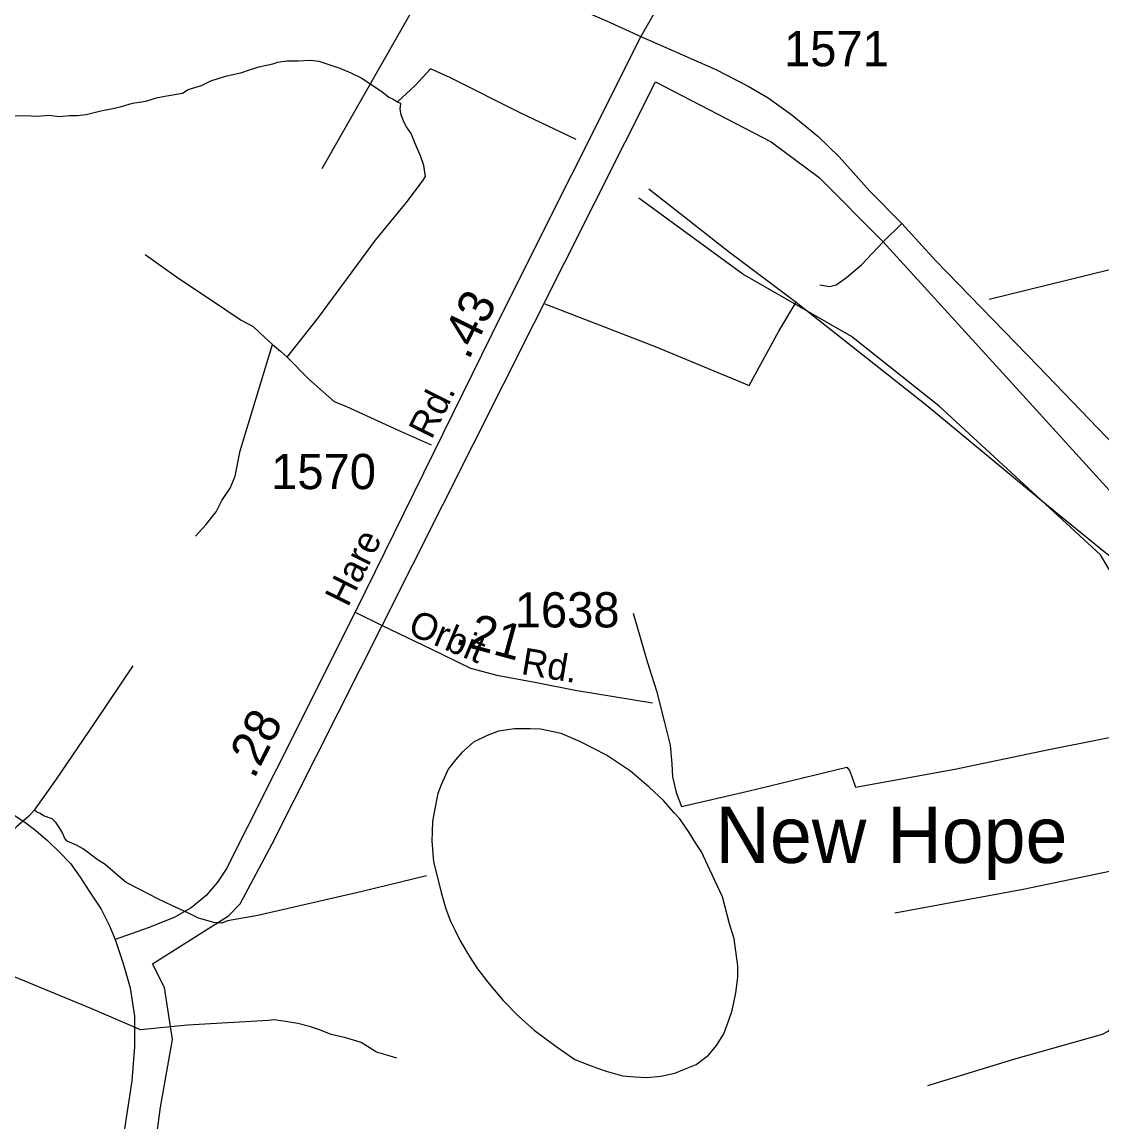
# Model space of a CAD drawing. Extents: x 2315291 to 2336543, y 597177 to 615230.
# Drawn here: x 2317961 to 2321792, y 602614 to 606517 of the extents above; entities that cross this region are included whole.
import ezdxf

# ---------------------------------------------------------------- set-up
doc = ezdxf.new("R2010")
doc.units = 0
for name, color, linetype in [('Exist Boundary Political Urban Extension UEB', 7, 'Continuous'), ('Exist Civil Demographics Community Label', 7, 'Continuous'), ('Exist Hydrographic Creek Single Shore', 7, 'Continuous'), ('Exist Hydrographic Misc Water Feature', 7, 'Continuous'), ('Exist Road Non-System Type 51', 7, 'Continuous'), ('Exist Road Secondary Mileage Hundredths English Label', 7, 'Continuous'), ('Exist Road Secondary Type 51 Attributed', 7, 'Continuous'), ('Exist Road Secondary Type 51 Label', 7, 'Continuous'), ('Exist Road Secondary Type 51 Number Label', 7, 'Continuous')]:
    doc.layers.add(name, color=color, linetype=linetype)

msp = doc.modelspace()

# ---------------------------------------------------------------- linework, layer by layer
at = {"layer": 'Exist Boundary Political Urban Extension UEB'}
for points in [[(2319238.3, 604375.7), (2320207.7, 606304.1), (2320618.3, 606091.8), (2320788.2, 605964.3), (2321014.8, 605737.8), (2321015.6, 605736.9)], [(2321015.6, 605736.9), (2321439.6, 605270.6), (2321864.3, 604803.4), (2322289.1, 604385.8), (2322926.3, 603720.4), (2323172.1, 603492.9)], [(2318542.1, 601594.9), (2318607.6, 601660.5), (2318494.4, 601816.2), (2318437.7, 601929.5), (2318395.3, 602099.4), (2318366.9, 602297.6), (2318423.6, 602453.3), (2318451.9, 602665.7), (2318494.4, 602906.3), (2318466, 603090.4), (2318423.6, 603175.3), (2318692.6, 603345.2), (2318735.1, 603387.7), (2318848.4, 603600.1), (2319238.3, 604375.7)]]:
    msp.add_lwpolyline(points, dxfattribs=at)
at = {"layer": 'Exist Hydrographic Creek Single Shore'}
msp.add_lwpolyline([(2321845.3, 604526.5), (2321786.3, 604625.7), (2321214.2, 605154), (2320903.3, 605400.6), (2320517.2, 605621.3), (2320148.3, 605891.9)], dxfattribs=at)
at = {"layer": 'Exist Hydrographic Misc Water Feature'}
msp.add_line((2321391.8, 605533.6), (2321819.7, 605637.9), dxfattribs=at)
for points in [[(2317922.7, 606184.2), (2317970.9, 606184.7), (2318014.8, 606183), (2318056.8, 606185.5), (2318092.7, 606181.7), (2318129, 606184.5), (2318156.7, 606184.7), (2318188.6, 606188.8), (2318240.5, 606201.7), (2318282.8, 606209.9), (2318313.9, 606216.2), (2318352.3, 606228.7), (2318400.1, 606235.3), (2318438.2, 606247.4), (2318467.7, 606253.9), (2318529.9, 606264.4), (2318549.7, 606276.8), (2318597.5, 606291.1), (2318630.9, 606307.6), (2318683, 606324.1), (2318740.9, 606336.9), (2318760.7, 606344.8), (2318800.7, 606357.5), (2318850.6, 606367.8), (2318868.6, 606374), (2318900.4, 606378.6), (2318940.4, 606379), (2318984, 606381.4), (2319014, 606377.7), (2319052.5, 606364.1), (2319088.4, 606352.6), (2319126.8, 606336.8), (2319166.7, 606317.4), (2319206.9, 606289.8), (2319237.1, 606270.3), (2319261.5, 606250.4), (2319277.7, 606242.7), (2319293, 606233.5), (2319303.9, 606226.9)], [(2319926.7, 606099.6), (2319725.7, 606195.5), (2319480.7, 606318.8), (2319410.1, 606350.1), (2319355, 606291.5), (2319293, 606233.5), (2319303.9, 606226.9)], [(2318901.4, 605327.3), (2319011.9, 605467.9), (2319214.7, 605742.4), (2319323.6, 605875.2), (2319381, 605951.8), (2319392.5, 605967.9), (2319385.9, 606007.8), (2319373.8, 606041.7), (2319355.2, 606085.4), (2319340.6, 606121.2), (2319324.2, 606145.2), (2319314.6, 606162.9), (2319306.2, 606186.9), (2319302.3, 606207), (2319303.9, 606226.9)], [(2320184.4, 605924.5), (2320470.9, 605699.8), (2320706.5, 605522.3)], [(2318398, 605691.4), (2318516.9, 605606.9), (2318629.3, 605532), (2318738.4, 605459.2), (2318780.4, 605435.9), (2318823.1, 605396.2), (2318849.3, 605372.4)], [(2319814.7, 605516.6), (2320206.4, 605365.2), (2320540, 605226.6), (2320645.6, 605419.6), (2320706.5, 605522.3)], [(2320706.5, 605522.3), (2321168.1, 605157.7), (2321601.7, 604798.4), (2321799.6, 604638.4), (2321978.8, 604500.3), (2322013.9, 604386.8), (2322068, 604193.7), (2322107.8, 604044.1)], [(2318576.4, 604692), (2318612.3, 604732), (2318649.4, 604778.8), (2318669.3, 604818.8), (2318698.6, 604863), (2318716.5, 604905.3), (2318735.1, 604995.4), (2318808.3, 605236.2), (2318849.3, 605372.4)], [(2318849.3, 605372.4), (2318877.2, 605348.7), (2318901.4, 605327.3)], [(2319412.8, 605014.6), (2319296.3, 605067.5), (2319113, 605151.5), (2319069.1, 605169), (2318978.5, 605249.9), (2318901.4, 605327.3)], [(2320128.8, 604418.6), (2320178.5, 604247.3), (2320211.5, 604143.8), (2320238.6, 604035.9), (2320259.7, 603950.4), (2320266, 603884.5), (2320268.5, 603838.3), (2320281.4, 603782.9), (2320299.9, 603733.1), (2320535.1, 603787.3), (2320886.3, 603873.1), (2320896.4, 603861.1), (2320904.6, 603839.2), (2320917.1, 603801.6), (2321270.2, 603865.3), (2321603, 603934.8), (2321948.3, 604004.5), (2322107.8, 604044.1)], [(2318353.5, 604231.6), (2318218, 604030.2), (2318080, 603827.1), (2318003.3, 603720.2)], [(2320445, 603412.8), (2320400.3, 603508.3), (2320371.6, 603571.8), (2320349.3, 603603.6), (2320326.7, 603641.4), (2320294.7, 603688.8), (2320274, 603710.6), (2320235.9, 603754.1), (2320185, 603801.4), (2320119, 603858.9), (2320034.1, 603915.8), (2319941.6, 603963), (2319873.4, 603992.3), (2319799.5, 604007.5), (2319763.2, 604008.9), (2319707.5, 604008.4), (2319651.5, 603999.8), (2319611.3, 603985.5), (2319562.3, 603960.9), (2319520.5, 603924.2), (2319498.7, 603898.3), (2319472.9, 603866.1), (2319447.5, 603809.9), (2319436, 603779.6), (2319430.2, 603749.6), (2319417.1, 603681.4), (2319415.5, 603641.5), (2319414, 603611.4), (2319420.8, 603537.3), (2319432.9, 603485.6), (2319447.7, 603427.8), (2319464.3, 603370.2), (2319480.9, 603326.3), (2319496.9, 603292.7), (2319515.5, 603256.6), (2319547.9, 603201), (2319576.4, 603157.4), (2319613.1, 603109.7), (2319623, 603098.1), (2319667.7, 603044.3), (2319722.2, 602989.1), (2319777, 602939.5), (2319809.2, 602916), (2319851, 602884.5), (2319922, 602835.3), (2319970.1, 602815.9), (2319998.2, 602806), (2320032.5, 602794.4), (2320090.3, 602777.2), (2320134.4, 602773.8), (2320178.3, 602772), (2320226.2, 602776.5), (2320276.1, 602787.3), (2320310.3, 602801.6), (2320351.7, 602818.1), (2320395.4, 602850.5), (2320424.7, 602884.5), (2320450.6, 602926.9), (2320467.8, 602975), (2320479.5, 603009.3), (2320492.8, 603071.4), (2320500, 603127.5), (2320499.8, 603167.3), (2320486.9, 603263.3), (2320470.5, 603316.9), (2320445, 603412.8)], [(2318003.3, 603720.2), (2317983.4, 603698.1), (2317965.8, 603681.7), (2317942, 603661.7), (2317926.2, 603645.5), (2317918.2, 603623.6), (2317906.7, 603607.5), (2317895, 603601.1), (2317866.7, 603596.8), (2317846.8, 603600.6), (2317800.7, 603594.2), (2317776.7, 603588.1), (2317746.8, 603589.3), (2317696.7, 603575), (2317671.3, 603566.7), (2317647.1, 603552.4), (2317621.5, 603544.1), (2317593.4, 603535.8), (2317579.2, 603537.9), (2317571.2, 603535.8), (2317561.6, 603535.7), (2317553.2, 603537.3)], [(2319395, 603487.2), (2319167.6, 603431.1), (2318797, 603346.9), (2318689.4, 603327.8), (2318669.3, 603319.5), (2318641, 603321.3), (2318587.1, 603336.7), (2318549.1, 603356.2), (2318492.5, 603381.8), (2318442.5, 603405.1), (2318378.3, 603438.3), (2318329.9, 603463.9), (2318291.8, 603495.6), (2318255.3, 603527), (2318226.8, 603544.7), (2318196.8, 603568.2), (2318174.7, 603584.1), (2318154.2, 603596.1), (2318120.8, 603609.7), (2318112.2, 603619.5), (2318104.2, 603639.4), (2318093.9, 603657.1), (2318082, 603675.1), (2318067.7, 603689.1), (2318037.3, 603700.5), (2318025.4, 603708.4), (2318011.5, 603714.1), (2318003.3, 603720.2)], [(2321057.3, 603355.5), (2321512.5, 603439.8), (2322051, 603551.8), (2322270.6, 603594.2)], [(2319290, 602840.4), (2319251.8, 602852.2), (2319217.8, 602861.8), (2319163.5, 602895.2), (2319109.3, 602912.6), (2319057.2, 602924.1), (2319019.1, 602939.6), (2318981, 602953), (2318938.7, 602962.6), (2318895.1, 602970), (2318871.1, 602974.1), (2318856.9, 602975.7), (2318834.8, 602973.8), (2318547.3, 602956.7), (2318381.4, 602940.7), (2318208.7, 603014.9), (2317821, 603174.6), (2317566.1, 603277.9), (2317571, 603403.7), (2317561.6, 603521.5), (2317553.2, 603537.3)], [(2321174, 602743), (2321479.3, 602836.2), (2321793.7, 602925.5), (2321815.8, 602937.6), (2321833.9, 602961.6), (2321851.5, 602983.7), (2321865, 602994.3), (2321879, 603000.3), (2321901.3, 603004.6), (2321927, 603000.8), (2321975.3, 602987.4), (2322013.3, 602975.6), (2322047.1, 602962), (2322075.6, 602948.4), (2322109.9, 602942.8), (2322135.5, 602941), (2322301.4, 602946.8), (2322481, 602960.8)]]:
    msp.add_lwpolyline(points, dxfattribs=at)
at = {"layer": 'Exist Road Non-System Type 51'}
for p, q in [((2319445.3, 606736.2), (2319024.4, 605995.8)), ((2321015.6, 605736.9), (2321081.3, 605802))]:
    msp.add_line(p, q, dxfattribs=at)
msp.add_lwpolyline([(2320790.6, 605583.5), (2320825.6, 605578.5), (2320849, 605583.5), (2320885.7, 605610.2), (2320939, 605655.2), (2321014, 605735.3), (2321015.6, 605736.9)], dxfattribs=at)
at = {"layer": 'Exist Road Secondary Type 51 Attributed'}
for points in [[(2320967.3, 607883), (2320750.6, 607501.9), (2320155.8, 606464.6)], [(2317800.8, 607001.1), (2318303.3, 606924.7), (2319093.5, 606793.7), (2319445.3, 606736.2), (2319537, 606711.2), (2319615.3, 606686.1), (2319658.7, 606671.1), (2319733.7, 606644.4), (2319831.3, 606606.3), (2319923.7, 606567.7), (2320033.8, 606521.3), (2320155.8, 606464.6)], [(2320155.8, 606464.6), (2319662, 605479), (2319142, 604422.2)], [(2320155.8, 606464.6), (2320422.4, 606348.1), (2320536.2, 606288.9), (2320607.5, 606247.9), (2320691, 606187.2), (2320783.6, 606111.2), (2320859.5, 606038.3), (2320968, 605916.9), (2321081.3, 605802), (2321202.4, 605668.6), (2321565.8, 605295.7), (2321867.6, 604981.3)], [(2316124.3, 604463.3), (2316481.2, 604353.3), (2316703.8, 604291.7), (2316831.6, 604256.4), (2316980.2, 604212.6), (2317151.6, 604138.2), (2317349.7, 604027.7), (2317559.2, 603913.3), (2317719.2, 603823.8), (2317844.9, 603757.1), (2317919.2, 603711.3), (2317974.4, 603675.1), (2318010.6, 603646.5), (2318050.6, 603612.2), (2318092.5, 603572.2), (2318132.5, 603530.3), (2318166.8, 603482.6), (2318199.2, 603433.1), (2318241.1, 603369.2), (2318271.6, 603310.1), (2318290.6, 603260.6)], [(2319142, 604422.2), (2318863.9, 603865.7), (2318759.2, 603658.9), (2318711.5, 603565.5), (2318686.8, 603514.1), (2318654.4, 603464.5), (2318614.4, 603416.9), (2318561.1, 603373), (2318500.1, 603338.7), (2318408.7, 603302.5), (2318290.6, 603260.6)], [(2319142, 604422.2), (2319238.3, 604375.7), (2319410.6, 604292.6), (2319551.5, 604224), (2319644.8, 604199.2), (2319780.1, 604174.4), (2319922.9, 604145.9), (2320197.2, 604101.1)], [(2318290.6, 603260.6), (2318319.2, 603175.8), (2318343.9, 603090), (2318359.2, 602989), (2318359.2, 602880.4), (2318349.7, 602760.3), (2318319.2, 602558.3), (2318302, 602434.4), (2318297.3, 602217.8), (2318323, 602068.5), (2318376.3, 601919.8), (2318441.1, 601784.5), (2318479.2, 601695.9), (2318498.2, 601663.5)]]:
    msp.add_lwpolyline(points, dxfattribs=at)

# ---------------------------------------------------------------- texts
at = {"layer": 'Exist Civil Demographics Community Label'}
msp.add_text('New Hope', height=200, dxfattribs=at).set_placement((2320420.6, 603532.7))
at = {"layer": 'Exist Road Secondary Mileage Hundredths English Label'}
for s, rotation, p in [('.43', 63.8016, (2319544.7, 605314)), ('.21', 344.7226, (2319492.7, 604311.3)), ('.28', 63.1334, (2318783.6, 603827.6))]:
    msp.add_text(s, height=125, rotation=rotation, dxfattribs=at).set_placement(p)
at = {"layer": 'Exist Road Secondary Type 51 Label'}
for s, rotation, p in [('Rd.', 63.4962, (2319413.1, 605032.3)), ('Hare', 63.4962, (2319116.5, 604437.4)), ('Orbit', 337.1201, (2319324.8, 604346.8)), ('Rd.', 350.564, (2319728.1, 604203.5))]:
    msp.add_text(s, height=95, rotation=rotation, dxfattribs=at).set_placement(p)
at = {"layer": 'Exist Road Secondary Type 51 Number Label'}
for s, p in [('1571', (2320663.6, 606359.7)), ('1570', (2318844.5, 604859.1)), ('1638', (2319708.5, 604368.4))]:
    msp.add_text(s, height=125, dxfattribs=at).set_placement(p)

doc.saveas('drawing.dxf')
